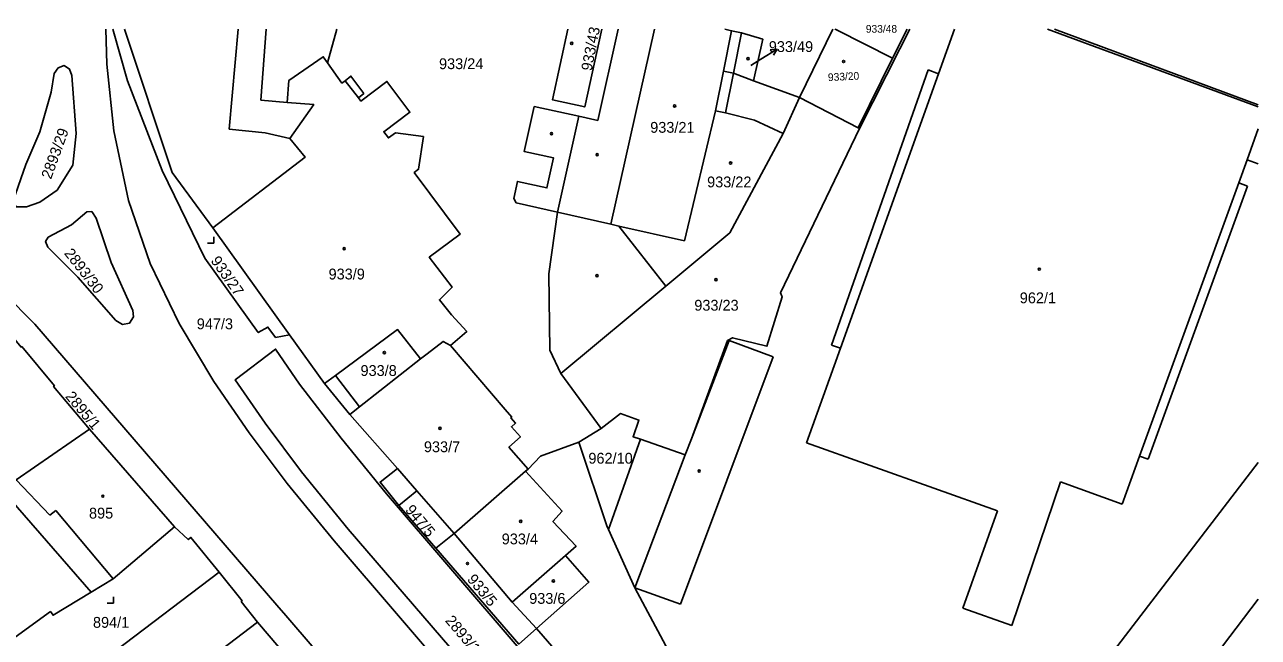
# Model space of a CAD drawing. Extents: x -496682 to -495776, y -1088797 to -1088018.
# Drawn here: x -496193.9 to -496000.3, y -1088115 to -1088018.8 of the extents above; entities that cross this region are included whole.
import ezdxf

# ---------------------------------------------------------------- set-up
doc = ezdxf.new("R2010")
doc.units = 0
for name, color, linetype in [('Hranice parcel', 7, 'Continuous'), ('Parcelní čísla', 7, 'Continuous'), ('Pop  PČ popisy', 7, 'Continuous'), ('Vnitřní kresba', 7, 'Continuous'), ('Značky budov', 7, 'Continuous'), ('Značky kultur', 7, 'Continuous')]:
    doc.layers.add(name, color=color, linetype=linetype)

msp = doc.modelspace()

# ---------------------------------------------------------------- linework, layer by layer
at = {"layer": 'Hranice parcel'}
for p, q in [((-496178.18, -1088019.49), (-496170.73, -1088041.99)), ((-496057.69, -1088024.02), (-496066.5, -1088019.6)), ((-496056.55, -1088022.57), (-496054.99, -1088019.49)), ((-496082.65, -1088026.4), (-496081.38, -1088020.07)), ((-496062.85, -1088035.07), (-496056.55, -1088022.57)), ((-496063.08, -1088034.95), (-496057.69, -1088024.02)), ((-496083.9, -1088032.61), (-496082.65, -1088026.4)), ((-496082.65, -1088026.4), (-496079.51, -1088027.56)), ((-496072.31, -1088030.21), (-496079.51, -1088027.56)), ((-496072.31, -1088030.21), (-496063.08, -1088034.95)), ((-496062.85, -1088035.07), (-496063.08, -1088034.95)), ((-496170.73, -1088041.99), (-496164.34, -1088050.67)), ((-496164.34, -1088050.67), (-496152.29, -1088067.45)), ((-496109.71, -1088073.53), (-496093.28, -1088059.84)), ((-496154.5, -1088067.86), (-496152.29, -1088067.45)), ((-496152.29, -1088067.45), (-496146.81, -1088075.09)), ((-496109.71, -1088073.53), (-496103.4, -1088082.18)), ((-496146.81, -1088075.09), (-496142.85, -1088079.96)), ((-496170.34, -1088097.61), (-496183.71, -1088082.3)), ((-496103.4, -1088082.18), (-496106.9, -1088084.33)), ((-496114.88, -1088088.54), (-496117.9, -1088085.09)), ((-496102.25, -1088098.03), (-496097.26, -1088083.87)), ((-496115.26, -1088088.87), (-496126.45, -1088098.68)), ((-496115.26, -1088088.87), (-496114.88, -1088088.54)), ((-496197.46, -1088091.77), (-496183.44, -1088107.88)), ((-496135.16, -1088094.24), (-496129.35, -1088100.96)), ((-496126.45, -1088098.68), (-496129.35, -1088100.96)), ((-496126.45, -1088098.68), (-496117.39, -1088109.46)), ((-496117.39, -1088109.46), (-496108.99, -1088102.12)), ((-496113.57, -1088113.57), (-496117.39, -1088109.46)), ((-496152.45, -1088118.29), (-496157.35, -1088112.6))]:
    msp.add_line(p, q, dxfattribs=at)
for points in [[(-496121.59, -1088147.94), (-496135.68, -1088131.58), (-496139.54, -1088127.1), (-496152.9, -1088111.52), (-496154.28, -1088109.93), (-496192.25, -1088065.81), (-496197.08, -1088060.92), (-496210.28, -1088048.82), (-496224.09, -1088036.2), (-496238.46, -1088023.17), (-496242.49, -1088019.49)], [(-496181.15, -1088019.49), (-496180.97, -1088024.95), (-496179.9, -1088035.45), (-496177.55, -1088046.36), (-496174.16, -1088056.24), (-496169.6, -1088065.68), (-496164.16, -1088074.78), (-496158.66, -1088082.86), (-496152.68, -1088090.79), (-496145.28, -1088099.81), (-496124.8, -1088123.7), (-496085.88, -1088168.81)], [(-496180.03, -1088019.49), (-496177.74, -1088027.59), (-496172.28, -1088041.67), (-496165.58, -1088055.45), (-496157.22, -1088067.11), (-496155.69, -1088066.25), (-496154.5, -1088067.86)], [(-496146.36, -1088024.77), (-496144.91, -1088019.49)], [(-496100.76, -1088019.49), (-496103.94, -1088033.79), (-496106.92, -1088033.15), (-496113.91, -1088031.64), (-496115.49, -1088038.67), (-496110.87, -1088039.68), (-496111.93, -1088044.4), (-496116.54, -1088043.38), (-496117.12, -1088046.07), (-496116.72, -1088046.75), (-496110.28, -1088048.21), (-496111.6, -1088057.9), (-496111.47, -1088069.87), (-496109.71, -1088073.53)], [(-496108.63, -1088019.49), (-496111.06, -1088030.56), (-496105.99, -1088031.67), (-496103.31, -1088019.49)], [(-496081.38, -1088020.07), (-496082.94, -1088019.72), (-496083.98, -1088019.49)], [(-496067.04, -1088019.49), (-496072.31, -1088030.21)], [(-496066.5, -1088019.6), (-496066.73, -1088019.49)], [(-496066.35, -1088019.49), (-496066.5, -1088019.6)], [(-496057.69, -1088024.02), (-496055.37, -1088019.49)], [(-496032.28, -1088019.49), (-496000.29, -1088031.36)], [(-496079.51, -1088027.56), (-496078.06, -1088021.06), (-496081.38, -1088020.07)], [(-496189.72, -1088029.38), (-496191.51, -1088035.6), (-496193.69, -1088040.71), (-496195.65, -1088046.45), (-496195.19, -1088047.37), (-496193.56, -1088047.37), (-496191.5, -1088046.66), (-496188.77, -1088044.74), (-496186.3, -1088040.83), (-496185.78, -1088035.84), (-496186.46, -1088026.73), (-496186.84, -1088025.75), (-496187.65, -1088025.2), (-496188.59, -1088025.53), (-496189.26, -1088026.45), (-496189.72, -1088029.38)], [(-496146.36, -1088024.77), (-496147.01, -1088023.8), (-496152.39, -1088027.53), (-496152.68, -1088030.97), (-496148.5, -1088031.32), (-496152.25, -1088036.62)], [(-496127.07, -1088069.16), (-496124.51, -1088066.95), (-496126.89, -1088064.3), (-496128.79, -1088061.95), (-496126.78, -1088059.98), (-496130.39, -1088055.28), (-496125.53, -1088051.64), (-496132.74, -1088041.98), (-496132.05, -1088041.46), (-496131.31, -1088036.33), (-496135.69, -1088035.73), (-496136.8, -1088036.56), (-496137.53, -1088035.58), (-496133.41, -1088032.52), (-496137.02, -1088027.69), (-496141.11, -1088030.77), (-496141.49, -1088030.26), (-496140.65, -1088029.57), (-496142.68, -1088026.85), (-496143.57, -1088027.57), (-496144.08, -1088027.93), (-496146.36, -1088024.77)], [(-496093.28, -1088059.84), (-496100.63, -1088050.4), (-496090.35, -1088052.7), (-496085.46, -1088032.3), (-496083.9, -1088032.61)], [(-496093.28, -1088059.84), (-496083.21, -1088051.44), (-496074.87, -1088035.85), (-496079.37, -1088033.74), (-496083.9, -1088032.61)], [(-496062.85, -1088035.07), (-496075.24, -1088060.86), (-496075, -1088061.51), (-496077.39, -1088069.25), (-496082.78, -1088067.93), (-496083.58, -1088068.36), (-496089.22, -1088083.77), (-496090.2, -1088086.33), (-496097.26, -1088083.87)], [(-496152.25, -1088036.62), (-496149.86, -1088039.59), (-496164.34, -1088050.67)], [(-496176.77, -1088064.66), (-496176.9, -1088063.64), (-496180.28, -1088056.11), (-496182.66, -1088049.14), (-496183.33, -1088048.12), (-496184.1, -1088048.13), (-496186.54, -1088050.2), (-496190.16, -1088052.15), (-496190.58, -1088052.82), (-496190.25, -1088053.68), (-496185.53, -1088058.39), (-496179.54, -1088065.21), (-496178.5, -1088065.84), (-496177.4, -1088065.63), (-496176.77, -1088064.66)], [(-496200.06, -1088062.62), (-496194.43, -1088069.4), (-496194.32, -1088069.3), (-496189.2, -1088075.46), (-496189.32, -1088075.56), (-496183.71, -1088082.3)], [(-496131.73, -1088071.25), (-496135.34, -1088066.64), (-496145.11, -1088073.84), (-496146.81, -1088075.09)], [(-496116.26, -1088116.72), (-496137.09, -1088092.45), (-496144.2, -1088083.68), (-496150.73, -1088075.21), (-496154.49, -1088069.71), (-496160.82, -1088074.53), (-496156.15, -1088081.34), (-496150.43, -1088088.98), (-496143.13, -1088097.97), (-496122.6, -1088121.81), (-496081, -1088170.14)], [(-496127.07, -1088069.16), (-496128.19, -1088068.5), (-496130.72, -1088070.46), (-496131.73, -1088071.25)], [(-496117.9, -1088085.09), (-496116.07, -1088083.5), (-496117.48, -1088081.89), (-496116.83, -1088081.32), (-496117.56, -1088080.48), (-496117.44, -1088080.37), (-496118.48, -1088079.17), (-496127.07, -1088069.16)], [(-496131.73, -1088071.25), (-496141.32, -1088078.77), (-496142.85, -1088079.96)], [(-496142.85, -1088079.96), (-496135.39, -1088088.47), (-496138.11, -1088090.59), (-496135.16, -1088094.24)], [(-496103.4, -1088082.18), (-496100.38, -1088079.84), (-496097.49, -1088080.85), (-496098.41, -1088083.47), (-496097.26, -1088083.87)], [(-496183.71, -1088082.3), (-496195.19, -1088090.23), (-496196.3, -1088091)], [(-496106.9, -1088084.33), (-496112.93, -1088086.52), (-496114.88, -1088088.54)], [(-496106.9, -1088084.33), (-496102.44, -1088097.6), (-496102.25, -1088098.03)], [(-496108.99, -1088102.12), (-496107.34, -1088100.65), (-496110.97, -1088096.75), (-496109.53, -1088095.14), (-496115.26, -1088088.87)], [(-496135.16, -1088094.24), (-496132.34, -1088091.95), (-496126.45, -1088098.68)], [(-496170.34, -1088097.61), (-496179.96, -1088105.77), (-496183.44, -1088107.88)], [(-496163.37, -1088104.73), (-496167.79, -1088099.27), (-496168.2, -1088099.6), (-496170.34, -1088097.61)], [(-496063.87, -1088167.88), (-496084, -1088133.61), (-496098.14, -1088107.2), (-496102.25, -1088098.03)], [(-496129.35, -1088100.96), (-496116.34, -1088116.02), (-496113.57, -1088113.57)], [(-496113.57, -1088113.57), (-496105.32, -1088106.28), (-496108.99, -1088102.12)], [(-496191.24, -1088126.97), (-496179.64, -1088117.06), (-496163.37, -1088104.73)], [(-496157.35, -1088112.6), (-496159.89, -1088109.34), (-496159.74, -1088109.21), (-496163.37, -1088104.73)], [(-496183.44, -1088107.88), (-496189.41, -1088111.49), (-496189.82, -1088110.92), (-496195.38, -1088114.92)], [(-496157.35, -1088112.6), (-496169.82, -1088122.1), (-496169.28, -1088122.83), (-496166.37, -1088126.68)], [(-496113.57, -1088113.57), (-496085.45, -1088145.89), (-496086.2, -1088146.36)]]:
    msp.add_lwpolyline(points, dxfattribs=at)
at = {"layer": 'Pop  PČ popisy'}
for p, q in [((-496078.34, -1088024.19), (-496075.79, -1088022.6)), ((-496075.79, -1088022.6), (-496076.91, -1088022.71)), ((-496075.79, -1088022.6), (-496076.38, -1088023.55)), ((-496079.92, -1088025.18), (-496078.34, -1088024.19))]:
    msp.add_line(p, q, dxfattribs=at)
at = {"layer": 'Vnitřní kresba'}
for p, q in [((-496160.36, -1088019.49), (-496161.76, -1088035.17)), ((-496155.95, -1088019.49), (-496156.79, -1088030.63)), ((-496095.02, -1088019.49), (-496101.89, -1088050.11)), ((-496050.48, -1088026.47), (-496047.98, -1088019.49)), ((-496033.36, -1088019.49), (-496000.29, -1088031.68)), ((-496082.94, -1088019.72), (-496084.21, -1088026.05)), ((-496084.21, -1088026.05), (-496085.46, -1088032.3)), ((-496084.21, -1088026.05), (-496082.65, -1088026.4)), ((-496067.26, -1088069.07), (-496052.12, -1088025.87)), ((-496065.86, -1088069.57), (-496050.48, -1088026.47)), ((-496052.12, -1088025.87), (-496050.48, -1088026.47)), ((-496143.57, -1088027.57), (-496141.49, -1088030.26)), ((-496156.79, -1088030.63), (-496152.68, -1088030.97)), ((-496074.87, -1088035.85), (-496072.31, -1088030.21)), ((-496106.92, -1088033.15), (-496110.28, -1088048.21)), ((-496000.29, -1088035.14), (-496002.04, -1088039.97)), ((-496161.76, -1088035.17), (-496156.14, -1088035.76)), ((-496156.14, -1088035.76), (-496152.25, -1088036.62)), ((-496002.04, -1088039.97), (-496003.36, -1088043.61)), ((-496002.04, -1088039.97), (-496000.29, -1088040.61)), ((-496003.36, -1088043.61), (-496018.92, -1088086.49)), ((-496001.98, -1088044.1), (-496017.57, -1088086.96)), ((-496003.36, -1088043.61), (-496001.98, -1088044.1)), ((-496110.28, -1088048.21), (-496101.89, -1088050.11)), ((-496100.63, -1088050.4), (-496101.89, -1088050.11)), ((-496089.22, -1088083.77), (-496083.31, -1088068.36)), ((-496083.31, -1088068.36), (-496076.43, -1088070.94)), ((-496068.56, -1088077.13), (-496065.86, -1088069.57)), ((-496065.86, -1088069.57), (-496067.26, -1088069.07)), ((-496076.43, -1088070.94), (-496090.95, -1088109.74)), ((-496145.11, -1088073.84), (-496141.32, -1088078.77)), ((-496071.17, -1088084.43), (-496068.56, -1088077.13)), ((-496041.22, -1088095.12), (-496071.17, -1088084.43)), ((-496098.14, -1088107.2), (-496090.2, -1088086.33)), ((-496018.92, -1088086.49), (-496021.66, -1088094.05)), ((-496017.57, -1088086.96), (-496018.92, -1088086.49)), ((-496132.34, -1088091.95), (-496135.39, -1088088.47)), ((-496052.38, -1088155.28), (-496000.29, -1088087.52)), ((-496189.91, -1088095.8), (-496195.19, -1088090.23)), ((-496031.33, -1088090.54), (-496038.99, -1088113.12)), ((-496021.66, -1088094.05), (-496031.33, -1088090.54)), ((-496188.97, -1088095.02), (-496189.91, -1088095.8)), ((-496179.96, -1088105.77), (-496188.97, -1088095.02)), ((-496046.67, -1088110.38), (-496041.22, -1088095.12)), ((-496090.95, -1088109.74), (-496098.14, -1088107.2)), ((-496038.99, -1088113.12), (-496046.67, -1088110.38)), ((-496000.29, -1088108.99), (-496041.78, -1088163.38))]:
    msp.add_line(p, q, dxfattribs=at)
at = {"layer": 'Značky budov'}
for centre in [(-496108.02, -1088021.71), (-496080.35, -1088024.1), (-496065.36, -1088024.55), (-496091.88, -1088031.52), (-496111.2, -1088035.89), (-496104.04, -1088039.19), (-496083.1, -1088040.49), (-496143.74, -1088053.95), (-496104.06, -1088058.18), (-496034.66, -1088057.16), (-496085.4, -1088058.81), (-496137.43, -1088070.25), (-496128.71, -1088082.15), (-496088.03, -1088088.85), (-496181.6, -1088092.8), (-496116.02, -1088096.76), (-496124.38, -1088103.36), (-496110.9, -1088106.11)]:
    msp.add_circle(centre, 0.175, dxfattribs=at)
at = {"layer": 'Značky kultur'}
for p, q in [((-496164.16, -1088053.06), (-496164.16, -1088052.06)), ((-496165.16, -1088053.06), (-496164.16, -1088053.06)), ((-496179.93, -1088109.61), (-496179.93, -1088108.61)), ((-496180.93, -1088109.61), (-496179.93, -1088109.61))]:
    msp.add_line(p, q, dxfattribs=at)

# ---------------------------------------------------------------- texts
at = {"layer": 'Parcelní čísla'}
for s, height, rotation, p in [('933/43', 1.7, 79, (-496104.9, -1088026.12)), ('933/20', 1.2, 3, (-496067.79, -1088027.64)), ('2893/29', 1.7, 70, (-496189.73, -1088043.13)), ('2893/30', 1.7, 308, (-496187.75, -1088054.69)), ('933/27', 1.7, 305, (-496164.75, -1088055.84)), ('2895/1', 1.7, 310, (-496187.58, -1088077.19)), ('947/5', 1.7, 310, (-496134.25, -1088095.01)), ('933/5', 1.7, 310, (-496124.53, -1088105.91)), ('2893/14', 1.7, 310, (-496127.97, -1088112.38))]:
    msp.add_text(s, height=height, rotation=rotation, dxfattribs=at).set_placement(p)
for s, height, p in [('933/48', 1.2, (-496061.88, -1088020.03)), ('933/49', 1.7, (-496077.1, -1088023.06)), ('933/24', 1.7, (-496128.85, -1088025.75)), ('933/21', 1.7, (-496095.71, -1088035.74)), ('933/22', 1.7, (-496086.78, -1088044.31)), ('933/9', 1.7, (-496146.18, -1088058.77)), ('933/23', 1.7, (-496088.79, -1088063.67)), ('962/1', 1.7, (-496037.72, -1088062.51)), ('947/3', 1.7, (-496166.86, -1088066.59)), ('933/8', 1.7, (-496141.17, -1088073.92)), ('933/7', 1.7, (-496131.22, -1088085.89)), ('962/10', 1.7, (-496105.41, -1088087.69)), ('895', 1.7, (-496183.77, -1088096.31)), ('933/4', 1.7, (-496119.01, -1088100.36)), ('933/6', 1.7, (-496114.7, -1088109.7)), ('894/1', 1.7, (-496183.15, -1088113.46))]:
    msp.add_text(s, height=height, dxfattribs=at).set_placement(p)

doc.saveas('drawing.dxf')
